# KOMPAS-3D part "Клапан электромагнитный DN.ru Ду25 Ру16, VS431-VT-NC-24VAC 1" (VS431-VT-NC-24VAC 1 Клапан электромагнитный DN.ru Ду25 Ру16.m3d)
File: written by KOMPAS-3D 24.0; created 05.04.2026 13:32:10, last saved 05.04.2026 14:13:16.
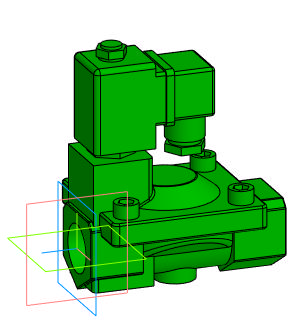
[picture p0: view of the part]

Document properties: Автор: artio; Полное имя файла: C:\Users\artio\OneDrive\Рабочий стол\Клапан электромагнитный DN.ru\VS431\VS431-VT-NC\VS431-VT-NC-24VAC\Ду25\VS431-VT-NC-24VAC 1 Клапан электромагнитный DN.ru Ду25 Ру16.m3d

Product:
- Body: Тело 1  | qty 1
    Масса: 1.729172
- Part/product: Клапан электромагнитный DN.ru Ду25 Ру16  | designation VS431-VT-NC-24VAC 1
    Масса: 1.267
    Раздел спецификации: Прочие изделия
    Примечание: D130-05514
    additional columns: ef56311e-7521-43dc-8291-0e6108b3d81d; artio; c; Шероховатость не задана; Да

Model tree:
1. Операция без истории:1

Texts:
  VS431-VT-NC-24VAC 1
